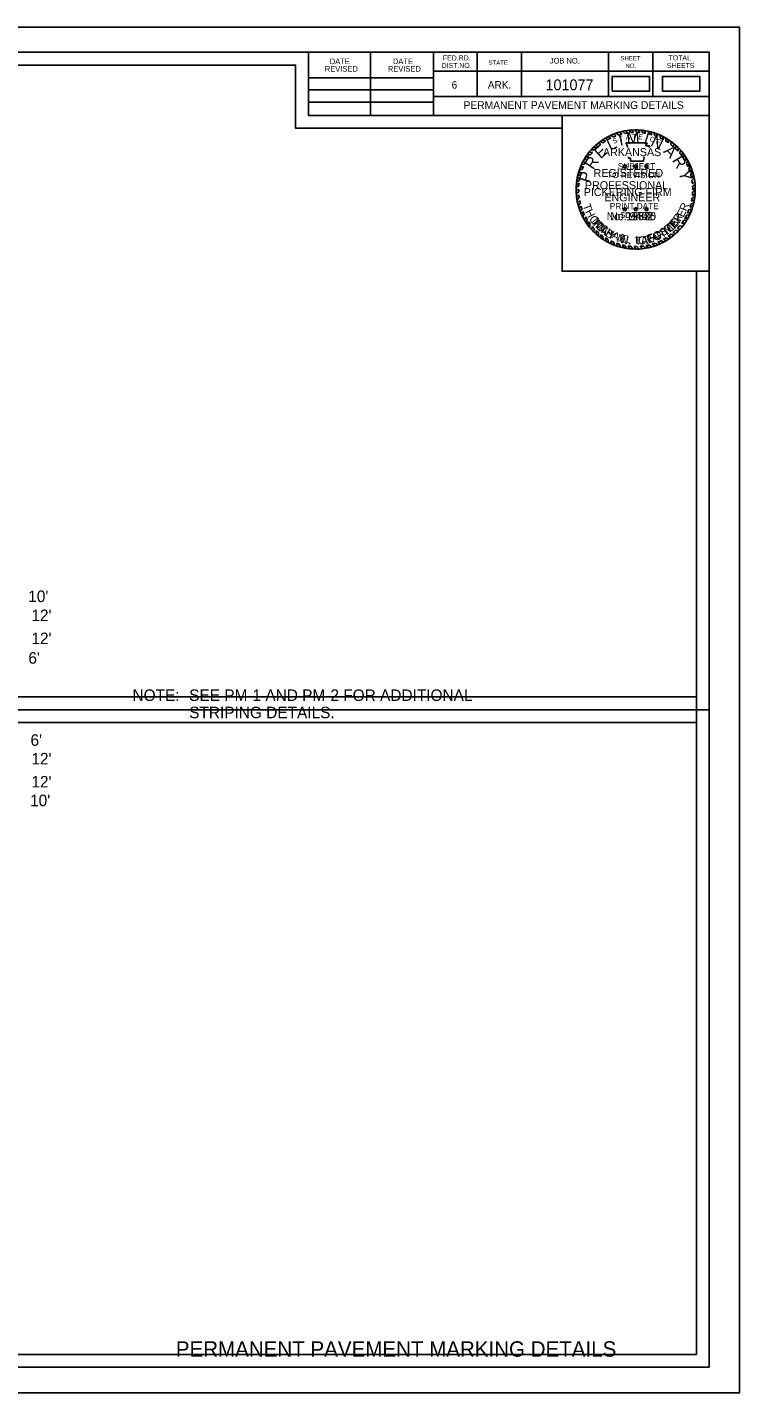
# Model space of a CAD drawing. Extents: x 1369895 to 1370228, y 380116 to 380329.
# Drawn here: x 1370116.7 to 1370228.1, y 380115.9 to 380329.2 of the extents above; entities that cross this region are included whole.
import ezdxf

# ---------------------------------------------------------------- set-up
doc = ezdxf.new("R2010")
doc.units = 0
for name, color, linetype in [('Default', 7, 'Continuous'), ('R_Border', 7, 'Continuous'), ('R_Border Notes', 7, 'Continuous'), ('R_Border Plan-Plan', 7, 'Continuous'), ('R_Border Title', 7, 'Continuous'), ('R_No Plot', 7, 'Continuous'), ('STAMP_PE_CRAFTON', 7, 'Continuous'), ('STAMP_PE_FOSTER', 7, 'Continuous'), ('STAMP_PE_SEAL-INFO', 7, 'Continuous'), ('STAMP_PE_TAEGTMEYER', 7, 'Continuous'), ('STAMP_PE_TXT', 7, 'Continuous'), ('STAMP_PRELIMINARY', 7, 'Continuous')]:
    doc.layers.add(name, color=color, linetype=linetype)

msp = doc.modelspace()

# ---------------------------------------------------------------- linework, layer by layer
at = {"layer": 'Default'}
for points in [[(1370208.12, 380319.26), (1370213.95, 380319.26), (1370213.95, 380321.57), (1370208.12, 380321.57)], [(1370215.99, 380319.27), (1370221.82, 380319.27), (1370221.82, 380321.58), (1370215.99, 380321.58)]]:
    msp.add_lwpolyline(points, close=True, dxfattribs=at)
at = {"layer": 'R_Border'}
for p, q in [((1369907.12, 380325.35), (1370223.3, 380325.35)), ((1370160.66, 380315.47), (1370160.66, 380325.35)), ((1370170.34, 380315.47), (1370170.34, 380325.35)), ((1370180.2, 380325.35), (1370180.2, 380315.47)), ((1370187.04, 380325.35), (1370187.04, 380318.41)), ((1370193.98, 380325.35), (1370193.98, 380318.41)), ((1370207.56, 380325.35), (1370207.56, 380318.41)), ((1370214.5, 380325.35), (1370214.5, 380318.41)), ((1370223.3, 380119.89), (1370223.3, 380325.35)), ((1370160.66, 380321.33), (1370180.2, 380321.33)), ((1370223.3, 380322.41), (1370180.2, 380322.41)), ((1370223.3, 380322.43), (1370223.3, 380322.43)), ((1370160.66, 380319.47), (1370180.2, 380319.47)), ((1370160.66, 380317.53), (1370180.2, 380317.53)), ((1370223.3, 380318.41), (1370180.2, 380318.41)), ((1370183.16, 380318.41), (1370223.3, 380318.41)), ((1370223.3, 380315.47), (1370160.66, 380315.47)), ((1370223.3, 380119.89), (1369907.12, 380119.89))]:
    msp.add_line(p, q, dxfattribs=at)
at = {"layer": 'R_Border Plan-Plan'}
msp.add_line((1369907.12, 380222.62), (1370223.3, 380222.62), dxfattribs=at)
at = {"layer": 'R_No Plot'}
for points in [[(1369894.71, 380329.25), (1370228.05, 380329.25), (1370228.05, 380115.91), (1369894.71, 380115.91)], [(1370221.3, 380224.62), (1369909.12, 380224.62), (1369909.12, 380323.35), (1370158.66, 380323.35), (1370158.66, 380313.47), (1370176.2, 380313.47), (1370200.3, 380313.47), (1370200.3, 380291.14), (1370221.3, 380291.14)], [(1369909.12, 380323.35), (1370158.66, 380323.35), (1370158.66, 380313.47), (1370176.2, 380313.47), (1370200.3, 380313.47), (1370200.3, 380291.14), (1370221.3, 380291.14), (1370221.3, 380121.89), (1369909.12, 380121.89)], [(1370200.3, 380315.47), (1370223.3, 380315.47), (1370223.3, 380291.14), (1370200.3, 380291.14)], [(1369909.12, 380220.62), (1370221.3, 380220.62), (1370221.3, 380121.89), (1369909.12, 380121.89)]]:
    msp.add_lwpolyline(points, close=True, dxfattribs=at)
at = {"layer": 'STAMP_PE_SEAL-INFO'}
for p, q in [((1370208.76, 380312.73), (1370209.14, 380312.42)), ((1370209.35, 380312.91), (1370209.64, 380312.56)), ((1370209.74, 380313.01), (1370210.1, 380312.66)), ((1370210.22, 380313.1), (1370210.52, 380312.74)), ((1370210.74, 380313.18), (1370211.02, 380312.79)), ((1370211.47, 380312.82), (1370211.16, 380313.22)), ((1370211.97, 380312.83), (1370211.69, 380313.24)), ((1370212.43, 380312.81), (1370212.17, 380313.23)), ((1370212.94, 380312.76), (1370212.64, 380313.2)), ((1370213.36, 380312.69), (1370213.1, 380313.15)), ((1370213.92, 380312.57), (1370213.75, 380313.03)), ((1370214.33, 380312.46), (1370214.17, 380312.93)), ((1370214.78, 380312.32), (1370214.64, 380312.8)), ((1370205.5, 380310.78), (1370205.96, 380310.64)), ((1370205.84, 380311.08), (1370206.37, 380310.98)), ((1370206.22, 380311.41), (1370206.68, 380311.21)), ((1370206.64, 380311.68), (1370207.08, 380311.48)), ((1370207.03, 380311.92), (1370207.46, 380311.7)), ((1370207.48, 380312.17), (1370207.94, 380311.95)), ((1370207.91, 380312.38), (1370208.3, 380312.11)), ((1370208.41, 380312.6), (1370208.71, 380312.27)), ((1370210.28, 380311.21), (1370213.62, 380311.21)), ((1370210.4, 380310.9), (1370210.28, 380311.21)), ((1370210.5, 380310.6), (1370210.4, 380310.9)), ((1370210.51, 380310.49), (1370210.5, 380310.6)), ((1370213.62, 380311.21), (1370213.39, 380310.71)), ((1370213.39, 380310.71), (1370214.03, 380310.71)), ((1370214.03, 380310.71), (1370213.88, 380310.49)), ((1370215.2, 380312.16), (1370215.05, 380312.65)), ((1370215.66, 380311.95), (1370215.55, 380312.45)), ((1370216.1, 380311.72), (1370216.02, 380312.23)), ((1370216.49, 380311.5), (1370216.45, 380312)), ((1370216.92, 380311.21), (1370216.89, 380311.72)), ((1370217.29, 380310.94), (1370217.32, 380311.43)), ((1370217.73, 380310.57), (1370217.75, 380311.09)), ((1370218.04, 380310.28), (1370218.11, 380310.78)), ((1370203.74, 380308.59), (1370204.23, 380308.61)), ((1370203.98, 380308.99), (1370204.5, 380309.02)), ((1370204.22, 380309.34), (1370204.72, 380309.33)), ((1370204.5, 380309.7), (1370205.04, 380309.73)), ((1370204.84, 380310.12), (1370205.36, 380310.08)), ((1370205.16, 380310.46), (1370205.71, 380310.42)), ((1370210.7, 380308.78), (1370210.67, 380308.99)), ((1370211.01, 380308.78), (1370210.7, 380308.78)), ((1370211.01, 380308.35), (1370211.01, 380308.78)), ((1370213.06, 380308.69), (1370213.04, 380308.35)), ((1370213.14, 380308.99), (1370213.06, 380308.69)), ((1370218.4, 380309.9), (1370218.47, 380310.43)), ((1370218.68, 380309.59), (1370218.81, 380310.06)), ((1370219, 380309.17), (1370219.14, 380309.67)), ((1370219.22, 380308.86), (1370219.4, 380309.32)), ((1370219.53, 380308.36), (1370219.71, 380308.85)), ((1370219.73, 380307.99), (1370219.96, 380308.44)), ((1370202.83, 380306.44), (1370203.3, 380306.6)), ((1370202.98, 380306.94), (1370203.47, 380307.08)), ((1370203.13, 380307.35), (1370203.64, 380307.49)), ((1370203.32, 380307.78), (1370203.82, 380307.88)), ((1370203.51, 380308.17), (1370204, 380308.23)), ((1370213.04, 380308.35), (1370211.01, 380308.35)), ((1370219.96, 380307.51), (1370220.19, 380307.99)), ((1370220.1, 380307.17), (1370220.36, 380307.6)), ((1370220.29, 380306.62), (1370220.57, 380307.1)), ((1370220.4, 380306.26), (1370220.7, 380306.71)), ((1370202.91, 380304.46), (1370202.48, 380304.21)), ((1370202.94, 380304.89), (1370202.51, 380304.61)), ((1370203, 380305.32), (1370202.56, 380305.1)), ((1370203.09, 380305.78), (1370202.62, 380305.53)), ((1370202.72, 380306.03), (1370203.19, 380306.22)), ((1370220.54, 380305.7), (1370220.85, 380306.15)), ((1370220.6, 380305.32), (1370220.96, 380305.67)), ((1370220.67, 380304.81), (1370221.04, 380305.15)), ((1370220.7, 380304.39), (1370221.09, 380304.68)), ((1370220.72, 380303.87), (1370221.12, 380304.19)), ((1370202.89, 380303.97), (1370202.48, 380303.63)), ((1370202.9, 380303.56), (1370202.5, 380303.24)), ((1370202.93, 380303.07), (1370202.56, 380302.71)), ((1370202.98, 380302.64), (1370202.63, 380302.26)), ((1370203.06, 380302.18), (1370202.72, 380301.81)), ((1370220.52, 380302.07), (1370220.98, 380302.27)), ((1370220.61, 380302.57), (1370221.06, 380302.79)), ((1370220.66, 380302.96), (1370221.1, 380303.22)), ((1370220.7, 380303.47), (1370221.12, 380303.74)), ((1370203.15, 380301.76), (1370202.84, 380301.35)), ((1370203.28, 380301.31), (1370202.98, 380300.9)), ((1370203.42, 380300.89), (1370203.14, 380300.48)), ((1370203.58, 380300.46), (1370203.32, 380300.04)), ((1370203.76, 380300.08), (1370203.53, 380299.62)), ((1370219.76, 380299.9), (1370220.25, 380299.96)), ((1370219.92, 380300.23), (1370220.41, 380300.33)), ((1370220.13, 380300.75), (1370220.62, 380300.88)), ((1370220.27, 380301.13), (1370220.76, 380301.33)), ((1370220.42, 380301.62), (1370220.89, 380301.82)), ((1370203.99, 380299.62), (1370203.8, 380299.13)), ((1370204.23, 380299.22), (1370204.04, 380298.75)), ((1370204.43, 380298.91), (1370204.32, 380298.35)), ((1370204.71, 380298.52), (1370204.61, 380297.99)), ((1370205.01, 380298.14), (1370204.93, 380297.62)), ((1370205.32, 380297.8), (1370205.25, 380297.28)), ((1370218.28, 380297.8), (1370218.76, 380297.71)), ((1370218.67, 380298.23), (1370219.13, 380298.15)), ((1370218.98, 380298.62), (1370219.48, 380298.63)), ((1370219.31, 380299.12), (1370219.79, 380299.11)), ((1370219.49, 380299.4), (1370219.99, 380299.45)), ((1370205.64, 380297.48), (1370205.61, 380296.95)), ((1370205.98, 380297.16), (1370205.98, 380296.63)), ((1370206.34, 380296.87), (1370206.36, 380296.34)), ((1370206.68, 380296.62), (1370206.72, 380296.1)), ((1370207.11, 380296.34), (1370207.17, 380295.82)), ((1370207.46, 380296.13), (1370207.55, 380295.62)), ((1370207.94, 380295.88), (1370208.1, 380295.36)), ((1370208.31, 380295.71), (1370208.49, 380295.2)), ((1370215.27, 380295.7), (1370215.69, 380295.44)), ((1370215.73, 380295.91), (1370216.21, 380295.7)), ((1370216.13, 380296.12), (1370216.55, 380295.89)), ((1370216.55, 380296.37), (1370217, 380296.17)), ((1370216.89, 380296.6), (1370217.33, 380296.41)), ((1370217.35, 380296.94), (1370217.82, 380296.79)), ((1370217.62, 380297.16), (1370218.09, 380297.04)), ((1370218.03, 380297.54), (1370218.47, 380297.4)), ((1370208.8, 380295.52), (1370209.01, 380295.02)), ((1370209.21, 380295.39), (1370209.44, 380294.9)), ((1370209.72, 380295.25), (1370209.93, 380294.78)), ((1370210.12, 380295.16), (1370210.37, 380294.7)), ((1370210.62, 380295.08), (1370210.86, 380294.64)), ((1370211.06, 380295.03), (1370211.33, 380294.6)), ((1370211.54, 380295), (1370211.84, 380294.59)), ((1370212, 380295), (1370212.34, 380294.61)), ((1370212.52, 380295.03), (1370212.85, 380294.65)), ((1370212.96, 380295.08), (1370213.33, 380294.72)), ((1370213.4, 380295.15), (1370213.79, 380294.81)), ((1370213.9, 380295.25), (1370214.27, 380294.93)), ((1370214.36, 380295.37), (1370214.77, 380295.08)), ((1370214.85, 380295.54), (1370215.29, 380295.27))]:
    msp.add_line(p, q, dxfattribs=at)
for radius, start, end in [(9.32, 105.2339, 109.0352), (9.32, 99.7525, 102.7765), (8.91, 98.258, 101.0329), (9.32, 93.9381, 96.5517), (8.91, 92.1102, 95.0367), (9.32, 87.7298, 90.6707), (8.91, 85.9628, 88.9097), (9.32, 81.9732, 84.8236), (8.91, 79.9264, 82.696), (9.32, 75.3125, 77.9426), (9.32, 69.6061, 72.3058), (9.32, 129.7326, 132.5376), (8.91, 127.5297, 130.9683), (9.32, 123.6199, 126.5906), (8.91, 121.9746, 125.11), (9.32, 117.6544, 120.8099), (8.91, 115.6869, 119.1583), (9.32, 111.3124, 114.7026), (8.91, 110.3086, 113.1659), (8.91, 104.0352, 107.3615), (8.91, 73.5575, 76.2314), (8.91, 67.6248, 70.504), (9.32, 63.1329, 66.2704), (8.91, 61.1558, 64.3784), (9.32, 56.9003, 60.0942), (8.91, 54.9238, 58.2702), (8.91, 48.3016, 52.0395), (9.32, 50.3492, 53.7159), (9.32, 44.3405, 47.3929), (9.32, 147.0072, 149.899), (9.32, 141.6056, 144.4486), (8.91, 145.0197, 148.2104), (8.91, 139.301, 142.5873), (9.32, 135.4021, 138.3031), (8.91, 133.1331, 136.2562), (8.91, 42.2212, 45.5512), (8.91, 36.135, 39.5311), (9.32, 38.1247, 41.2316), (8.91, 29.9032, 33.6645), (9.32, 31.9614, 35.4294), (9.32, 25.9391, 29.0125), (9.32, 164.3068, 166.894), (9.32, 158.4077, 161.0701), (8.91, 162.4331, 165.0013), (9.32, 152.864, 155.5189), (8.91, 156.3402, 159.2319), (8.91, 151.0315, 153.573), (8.91, 23.7732, 27.2211), (8.91, 17.6802, 21.4251), (9.32, 19.9538, 23.3141), (9.32, 13.8421, 17.4447), (9.32, 175.7409, 178.2066), (9.32, 170.0003, 172.6878), (8.91, 173.73, 176.4734), (8.91, 167.9048, 170.9039), (8.91, 11.5444, 15.2364), (8.91, 5.7599, 9.0606), (8.91, 359.7329, 3.0639), (9.32, 7.5852, 10.8621), (9.32, 1.7215, 4.7268), (9.32, 181.7251, 184.1626), (9.32, 187.4204, 190.1927), (8.91, 179.6454, 182.2633), (8.91, 185.4539, 188.234), (8.91, 191.2274, 193.9858), (8.91, 348.0778, 351.3435), (8.91, 353.8632, 357.1274), (9.32, 349.8305, 353.0885), (9.32, 355.7156, 358.9569), (9.32, 193.0369, 195.9973), (9.32, 198.8967, 201.6281), (8.91, 196.9675, 199.8353), (9.32, 204.5479, 207.4328), (8.91, 202.7761, 205.4791), (8.91, 329.5549, 333.2076), (8.91, 335.6038, 339.1858), (9.32, 331.4037, 334.9332), (8.91, 341.777, 345.0925), (9.32, 337.3837, 340.9933), (9.32, 343.8925, 347.035), (9.32, 210.8636, 213.6571), (8.91, 208.7883, 211.7934), (9.32, 216.6115, 219.491), (8.91, 214.1838, 217.2747), (8.91, 220.3909, 223.3056), (8.91, 316.6531, 320.3711), (9.32, 318.2846, 321.8043), (8.91, 323.5851, 327.4407), (9.32, 325.4405, 328.9872), (9.32, 222.48, 225.3801), (9.32, 228.3665, 231.348), (8.91, 226.2494, 229.2407), (8.91, 232.229, 234.9336), (9.32, 234.295, 236.9452), (8.91, 238.2223, 240.8353), (9.32, 240.1977, 242.8613), (8.91, 244.3204, 246.9486), (8.91, 292.8745, 296.1185), (9.32, 294.6481, 298.2166), (8.91, 299.0768, 302.1724), (9.32, 300.621, 303.8703), (8.91, 304.823, 308.5143), (9.32, 306.3721, 310.208), (8.91, 310.7744, 314.3161), (9.32, 312.4518, 315.6633), (9.32, 246.576, 249.1558), (8.91, 250.3491, 253.1216), (9.32, 252.5967, 255.3252), (8.91, 256.505, 259.1192), (9.32, 258.4433, 261.1398), (8.91, 262.3783, 265.2012), (9.32, 264.1978, 267.1009), (8.91, 268.3215, 271.277), (9.32, 270.2548, 273.3361), (8.91, 274.6157, 277.4486), (9.32, 276.4239, 279.4357), (8.91, 280.3459, 283.5814), (9.32, 282.3199, 285.3702), (8.91, 286.6423, 289.9783), (9.32, 288.5709, 291.9733)]:
    msp.add_arc((1370211.8, 380303.91), radius, start, end, dxfattribs=at)
at = {"layer": 'STAMP_PE_TXT'}
for p, q in [((1370209.98, 380307.49), (1370209.78, 380307.63)), ((1370209.78, 380307.63), (1370210.03, 380307.63)), ((1370209.91, 380307.25), (1370209.98, 380307.49)), ((1370210.1, 380307.4), (1370209.91, 380307.25)), ((1370210.03, 380307.63), (1370210.1, 380307.86)), ((1370210.1, 380307.86), (1370210.18, 380307.63)), ((1370210.3, 380307.25), (1370210.1, 380307.4)), ((1370210.18, 380307.63), (1370210.43, 380307.63)), ((1370210.43, 380307.63), (1370210.23, 380307.49)), ((1370210.23, 380307.49), (1370210.3, 380307.25)), ((1370211.68, 380307.49), (1370211.48, 380307.63)), ((1370211.48, 380307.63), (1370211.73, 380307.63)), ((1370211.6, 380307.25), (1370211.68, 380307.49)), ((1370211.8, 380307.4), (1370211.6, 380307.25)), ((1370211.73, 380307.63), (1370211.8, 380307.86)), ((1370211.8, 380307.86), (1370211.88, 380307.63)), ((1370212, 380307.25), (1370211.8, 380307.4)), ((1370211.88, 380307.63), (1370212.12, 380307.63)), ((1370212.12, 380307.63), (1370211.92, 380307.49)), ((1370211.92, 380307.49), (1370212, 380307.25)), ((1370213.38, 380307.49), (1370213.18, 380307.63)), ((1370213.18, 380307.63), (1370213.42, 380307.63)), ((1370213.3, 380307.25), (1370213.38, 380307.49)), ((1370213.5, 380307.4), (1370213.3, 380307.25)), ((1370213.42, 380307.63), (1370213.5, 380307.86)), ((1370213.5, 380307.86), (1370213.58, 380307.63)), ((1370213.7, 380307.25), (1370213.5, 380307.4)), ((1370213.58, 380307.63), (1370213.82, 380307.63)), ((1370213.82, 380307.63), (1370213.62, 380307.49)), ((1370213.62, 380307.49), (1370213.7, 380307.25)), ((1370209.98, 380300.78), (1370209.78, 380300.92)), ((1370209.78, 380300.92), (1370210.03, 380300.92)), ((1370209.91, 380300.55), (1370209.98, 380300.78)), ((1370210.1, 380300.69), (1370209.91, 380300.55)), ((1370210.03, 380300.92), (1370210.1, 380301.16)), ((1370210.1, 380301.16), (1370210.18, 380300.92)), ((1370210.3, 380300.55), (1370210.1, 380300.69)), ((1370210.18, 380300.92), (1370210.43, 380300.92)), ((1370210.43, 380300.92), (1370210.23, 380300.78)), ((1370210.23, 380300.78), (1370210.3, 380300.55)), ((1370211.68, 380300.78), (1370211.48, 380300.92)), ((1370211.48, 380300.92), (1370211.73, 380300.92)), ((1370211.6, 380300.55), (1370211.68, 380300.78)), ((1370211.8, 380300.69), (1370211.6, 380300.55)), ((1370211.73, 380300.92), (1370211.8, 380301.16)), ((1370211.8, 380301.16), (1370211.88, 380300.92)), ((1370212, 380300.55), (1370211.8, 380300.69)), ((1370211.88, 380300.92), (1370212.12, 380300.92)), ((1370212.12, 380300.92), (1370211.92, 380300.78)), ((1370211.92, 380300.78), (1370212, 380300.55)), ((1370213.38, 380300.78), (1370213.18, 380300.92)), ((1370213.18, 380300.92), (1370213.42, 380300.92)), ((1370213.3, 380300.55), (1370213.38, 380300.78)), ((1370213.5, 380300.69), (1370213.3, 380300.55)), ((1370213.42, 380300.92), (1370213.5, 380301.16)), ((1370213.5, 380301.16), (1370213.58, 380300.92)), ((1370213.7, 380300.55), (1370213.5, 380300.69)), ((1370213.58, 380300.92), (1370213.82, 380300.92)), ((1370213.82, 380300.92), (1370213.62, 380300.78)), ((1370213.62, 380300.78), (1370213.7, 380300.55))]:
    msp.add_line(p, q, dxfattribs=at)
at = {"layer": 'STAMP_PRELIMINARY'}
msp.add_circle((1370211.8, 380303.91), 9.32, dxfattribs=at)

# ---------------------------------------------------------------- texts
at = {"layer": 'Default'}
for s, p in [("10'", (1370116.88, 380239.44)), ("12'", (1370117.37, 380236.47)), ("12'", (1370117.37, 380232.87)), ("6'", (1370116.9, 380229.81)), ("6'", (1370117.23, 380216.98)), ("12'", (1370117.37, 380214.07)), ("12'", (1370117.37, 380210.47)), ("10'", (1370117.16, 380207.55))]:
    msp.add_text(s, height=1.8, rotation=360, dxfattribs=at).set_placement(p)
for s, p in [('NOTE:', (1370133.17, 380223.99)), ('SEE PM-1 AND PM-2 FOR ADDITIONAL', (1370142.03, 380223.99)), ('STRIPING DETAILS.', (1370142.03, 380221.29))]:
    msp.add_text(s, height=1.8, dxfattribs=at).set_placement(p)
at = {"layer": 'R_Border'}
for s, height, p in [('DATE', 0.879, (1370164, 380323.49)), ('DATE', 0.879, (1370173.86, 380323.49)), ('DIST.NO.', 0.782, (1370181.48, 380322.89)), ('FED.RD.', 0.782, (1370181.68, 380324.07)), ('STATE', 0.684, (1370188.8, 380323.39)), ('JOB NO.', 0.879, (1370198.38, 380323.59)), ('SHEET', 0.684, (1370209.42, 380324.07)), ('NO.', 0.684, (1370210.2, 380322.89)), ('SHEETS', 0.782, (1370216.66, 380322.89)), ('TOTAL', 0.782, (1370216.94, 380324.07)), ('REVISED', 0.879, (1370163.22, 380322.31)), ('REVISED', 0.879, (1370173.08, 380322.31)), ('6', 1.17, (1370183.04, 380319.67)), ('ARK.', 1.172, (1370188.7, 380319.67))]:
    msp.add_text(s, height=height, dxfattribs=at).set_placement(p)
at = {"layer": 'R_Border Notes'}
for s, height, p in [('101077', 1.68, (1370197.71, 380319.42)), ('PERMANENT PAVEMENT MARKING DETAILS', 1.2, (1370184.9, 380316.49))]:
    msp.add_text(s, height=height, dxfattribs=at).set_placement(p)
at = {"layer": 'R_Border Title'}
msp.add_text('PERMANENT PAVEMENT MARKING DETAILS', height=2.4, dxfattribs=at).set_placement((1370139.94, 380121.54))
at = {"layer": 'STAMP_PE_CRAFTON'}
msp.add_text('No. 12370', height=1.25, dxfattribs=at).set_placement((1370207.26, 380299.11))
for s, rotation, p in [('T', 310.7442, (1370204.77, 380298.81)), ('O', 317.6422, (1370205.44, 380298)), ('N', 324.4537, (1370206.28, 380297.22)), ('T', 34.1136, (1370216.38, 380296.55)), ('O', 41.8391, (1370217.24, 380297.16)), ('N', 49.2411, (1370218.08, 380297.94)), ('Y', 331.1686, (1370207.31, 380296.5)), ('N', 347.4752, (1370209.37, 380295.58)), ('C', 6.0117, (1370212.27, 380295.26)), ('R', 14.8189, (1370213.37, 380295.37)), ('A', 20.5125, (1370214.48, 380295.67)), ('F', 28.7821, (1370215.46, 380296.04)), ('.', 356.8926, (1370210.6, 380295.31))]:
    msp.add_text(s, height=1.25, rotation=rotation, dxfattribs=at).set_placement(p)
at = {"layer": 'STAMP_PE_FOSTER'}
msp.add_text('No. 9402', height=1.25, dxfattribs=at).set_placement((1370207.79, 380299.11))
for s, rotation, p in [('R', 54.5031, (1370218.53, 380298.73)), ('M', 308.339, (1370204.92, 380298.94)), ('I', 314.1842, (1370205.72, 380298)), ('C', 319.8733, (1370206.07, 380297.65)), ('H', 327.7235, (1370207, 380296.91)), ('S', 31.7234, (1370215.99, 380296.53)), ('T', 39.4194, (1370216.94, 380297.15)), ('E', 46.9613, (1370217.8, 380297.9)), ('A', 335.7276, (1370207.98, 380296.33)), ('E', 343.5779, (1370209.12, 380295.86)), ('L', 350.8115, (1370210.18, 380295.58)), ('L', 1.2666, (1370211.72, 380295.42)), ('.', 6.8035, (1370212.76, 380295.48)), ('F', 15.8691, (1370213.84, 380295.67)), ('O', 23.719, (1370214.88, 380296))]:
    msp.add_text(s, height=1.2, rotation=rotation, dxfattribs=at).set_placement(p)
at = {"layer": 'STAMP_PE_TAEGTMEYER'}
for s, rotation, p in [('T', 289.646, (1370203.5, 380301.42)), ('H', 296.7339, (1370203.86, 380300.44)), ('Y', 53.9986, (1370218.58, 380298.51)), ('E', 63.0984, (1370219.25, 380299.45)), ('R', 69.57, (1370219.75, 380300.43)), ('O', 303.7708, (1370204.45, 380299.33)), ('M', 314.2033, (1370205.1, 380298.38)), ('A', 321.0594, (1370206.07, 380297.42)), ('T', 31.466, (1370215.9, 380296.27)), ('M', 39.3, (1370216.8, 380296.81)), ('E', 46.8094, (1370217.84, 380297.69)), ('S', 327.8239, (1370206.89, 380296.77)), ('N', 344.2727, (1370208.79, 380295.77)), ('T', 3.0061, (1370211.67, 380295.24)), ('A', 8.9826, (1370212.71, 380295.29)), ('E', 17.6836, (1370213.75, 380295.45)), ('G', 23.3052, (1370214.8, 380295.78)), ('.', 350.6464, (1370210, 380295.43))]:
    msp.add_text(s, height=1.25, rotation=rotation, dxfattribs=at).set_placement(p)
msp.add_text('No. 19605', height=1.25, dxfattribs=at).set_placement((1370207.26, 380299.11))
at = {"layer": 'STAMP_PE_TXT'}
for s, rotation, p in [('S', 23.5541, (1370208.4, 380311.02)), ('T', 16.311, (1370209.32, 380311.39)), ('A', 9.0679, (1370210.29, 380311.64)), ('T', 1.8248, (1370211.27, 380311.77)), ('E', 355.2002, (1370212.18, 380311.78)), ('O', 342.2506, (1370213.91, 380311.5)), ('F', 335.0075, (1370214.87, 380311.17))]:
    msp.add_text(s, height=0.781, rotation=rotation, dxfattribs=at).set_placement(p)
for s, p in [('ARKANSAS', (1370206.69, 380309.12)), ('REGISTERED', (1370205.22, 380305.86)), ('PROFESSIONAL', (1370203.87, 380303.95)), ('ENGINEER', (1370206.91, 380302.05))]:
    msp.add_text(s, height=1.25, dxfattribs=at).set_placement(p)
at = {"layer": 'STAMP_PRELIMINARY'}
for s, rotation, p in [('M', 3.1074, (1370210.44, 380311.01)), ('I', 342.3164, (1370212.91, 380311.08)), ('E', 42.3578, (1370206.33, 380308.61)), ('L', 25.513, (1370207.81, 380309.94)), ('I', 12.5248, (1370209.34, 380310.7)), ('N', 333.9382, (1370214.01, 380310.8)), ('A', 315.6579, (1370216.05, 380309.78)), ('R', 56.2292, (1370205.17, 380306.88)), ('R', 301.3831, (1370217.42, 380308.46)), ('P', 73.913, (1370204.62, 380304.86)), ('Y', 283.2593, (1370218.5, 380306.68))]:
    msp.add_text(s, height=1.8, rotation=rotation, dxfattribs=at).set_placement(p)
for s, height, p in [('TO REVISION', 0.96, (1370207.34, 380305.68)), ('SUBJECT', 0.96, (1370209, 380307.06)), ('PICKERING FIRM', 1.25, (1370203.68, 380302.88)), ('PRINT DATE', 0.96, (1370207.76, 380300.83)), ('$DATE$', 0.96, (1370209.44, 380299.45))]:
    msp.add_text(s, height=height, dxfattribs=at).set_placement(p)

doc.saveas('drawing.dxf')
